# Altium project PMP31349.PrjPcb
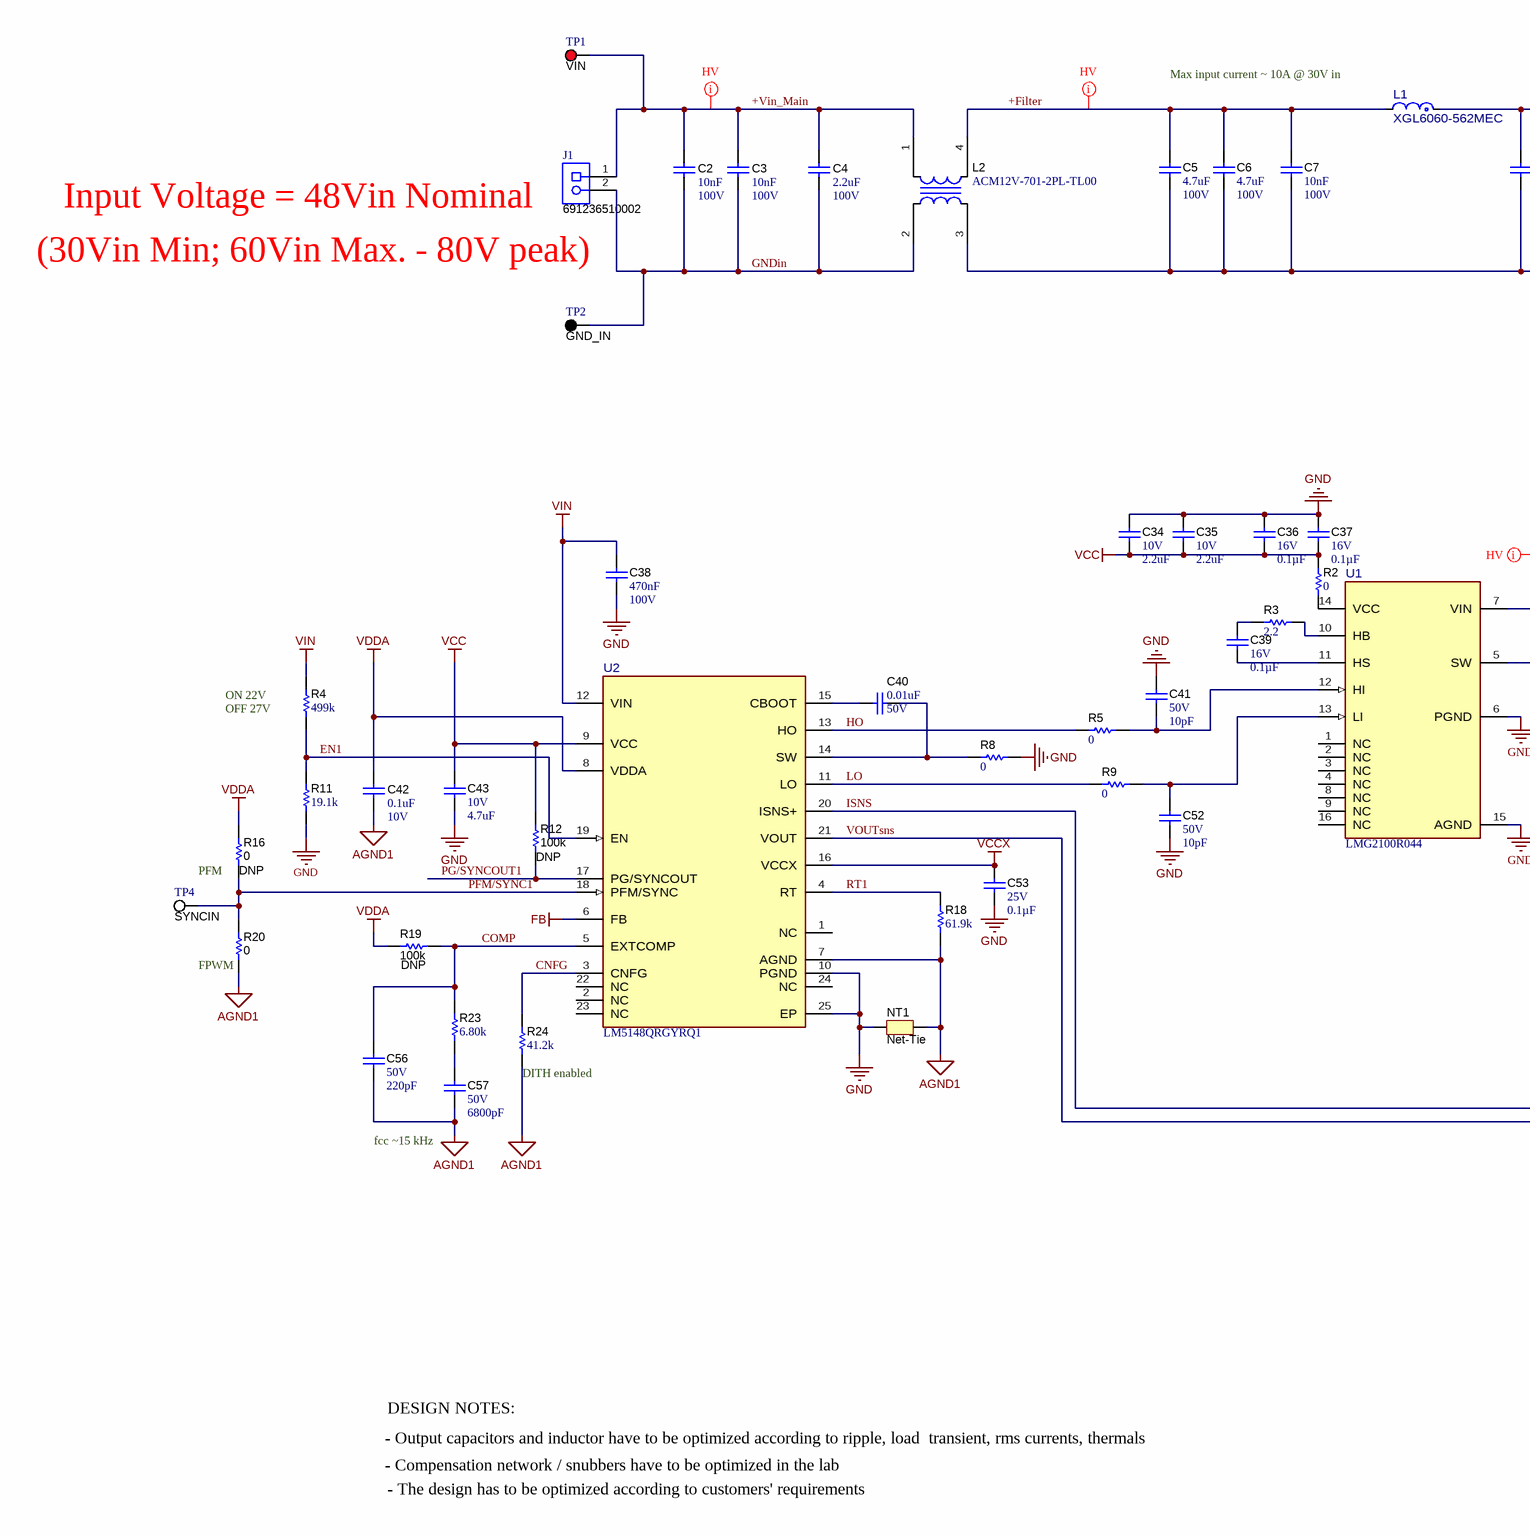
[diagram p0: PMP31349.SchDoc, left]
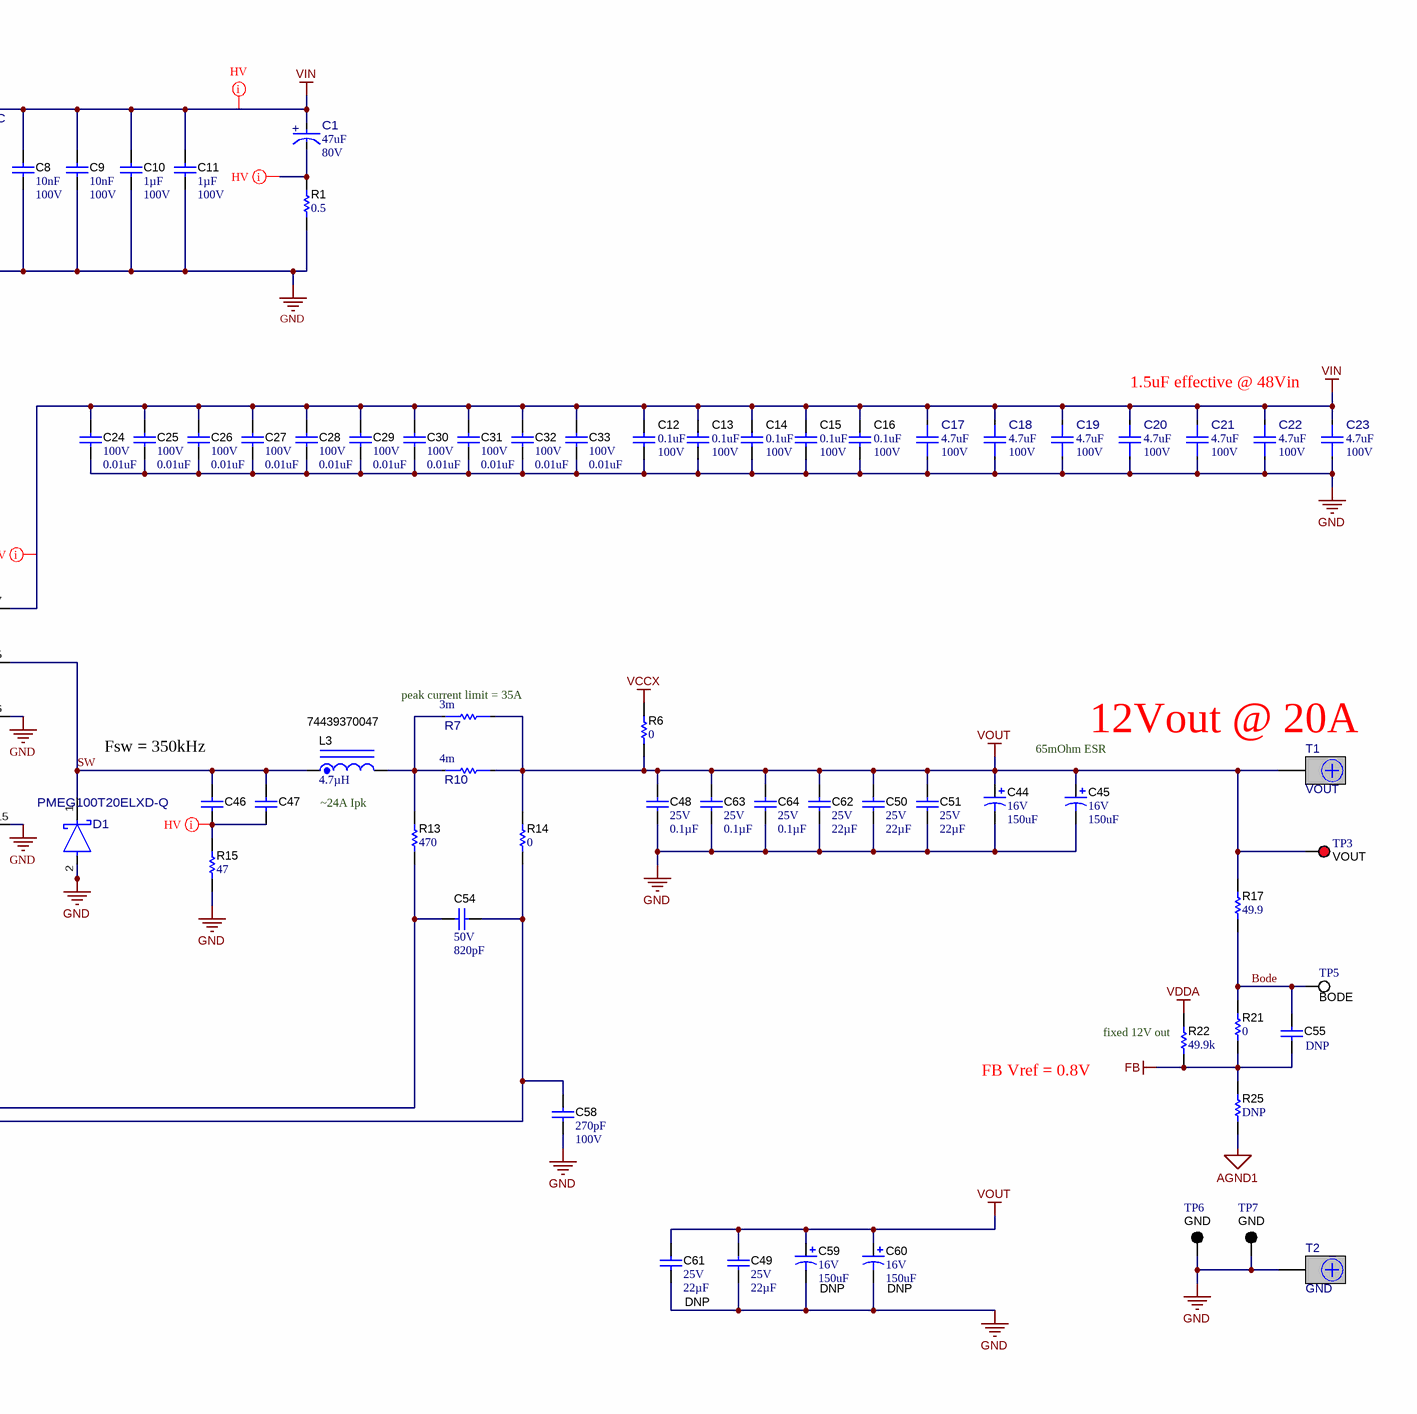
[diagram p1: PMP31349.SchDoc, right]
CopyrightYear: 2024; PCB_Layout: Who did the Layout?; PCB_Rev: B; PRJ_Customer: Public Release; PRJ_Engineer: S.Panaro; PRJ_Number: PMP31349; PRJ_Title: 240W GaN Board; SCH_Rev: B; TechSupport: http://www.ti.com/support; TID: N/A
2 sheets, 110 parts. Net scope: global (net labels, ports and power ports of the same name join across sheets).
Board file: PMP31349.PcbDoc
Sheets:
  PMP31349.SchDoc
  PMP31349_Hardware.SchDoc

## Sheet PMP31349.SchDoc
size 558 x 431 mm; Date: Not shown in title block; ApprovedBy: Not shown in title block; CheckedBy: Not shown in title block; Author: Not shown in title block; CompanyName: Not shown in title block; Engineer: Not shown in title block; Organization: Not shown in title block; Address1: Not shown in title block; Address2: Not shown in title block; Address3: Not shown in title block; Address4: Not shown in title block; DocumentNumber: 1; Revision: Use project parameter SCH_Rev; SheetNumber: 1; SheetTotal: 2; PageSetup: Record=PageOptions¦CenterHorizontal=True¦CenterVertical=True¦PrintScale=1.00¦XCorrection=1.00¦YCorrection=1.00¦PrintKind=0¦BorderSize=5000000¦LeftOffset=0¦BottomOffset=0¦Orientation=2¦PaperLength=1000¦PaperWidth=1000¦Scale=100¦PaperSource=15¦PrintQuality=600¦MediaType=1¦DitherType=10¦PaperKind=Letter¦PrintScaleMode=1; SPICEModelCacheOPLTMGFQ: <root> / <DocumentId>OPLTMGFQ</DocumentId> / </root>

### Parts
C1  ValueDisplayed: 47uF  VDC_V: 80V  [FP-EEHZA1K470P_RADIAL_SMT-MFG]  (hidden comment: EEHZA1K470P)
C2  Cap_F: 10nF  VDC_V: 100V  [0603_HV]  (hidden comment: GCM188R72A103KA37J)
C3  Cap_F: 10nF  VDC_V: 100V  [0603_HV]  (hidden comment: GCM188R72A103KA37J)
C4  VDC_V: 100V  ValueDisplayed: 2.2uF  [1206_180]  (hidden comment: CGA5L3X7S2A225K160AB)
C5  ValueDisplayed: 4.7uF  VDC_V: 100V  [1210_220]  (hidden comment: C3225X7S2A475K200AB)
C6  ValueDisplayed: 4.7uF  VDC_V: 100V  [1210_220]  (hidden comment: CGA6M3X7S2A475K200AB)
C7  Cap_F: 10nF  VDC_V: 100V  [0603L]  (hidden comment: GCM188R72A103KA37J)
C8  Cap_F: 10nF  VDC_V: 100V  [0603L]  (hidden comment: GCM188R72A103KA37J)
C9  Cap_F: 10nF  VDC_V: 100V  [0603L]  (hidden comment: GCM188R72A103KA37J)
C10  Cap_F: 1µF  VDC_V: 100V  [0805_150]  (hidden comment: 08051C105K4Z2A)
C11  Cap_F: 1µF  VDC_V: 100V  [0805_150]  (hidden comment: 08051C105K4Z2A)
C12  VDC_V: 100V  ValueDisplayed: 0.1uF  [0603L]  (hidden comment: GCJ188R72A104KA01D)
C13  VDC_V: 100V  ValueDisplayed: 0.1uF  [0603L]  (hidden comment: GCJ188R72A104KA01D)
C14  VDC_V: 100V  ValueDisplayed: 0.1uF  [0603L]  (hidden comment: GCJ188R72A104KA01D)
C15  VDC_V: 100V  ValueDisplayed: 0.1uF  [0603L]  (hidden comment: GCJ188R72A104KA01D)
C16  VDC_V: 100V  ValueDisplayed: 0.1uF  [0603L]  (hidden comment: GCJ188R72A104KA01D)
C17  ValueDisplayed: 4.7uF  VDC_V: 100V  [FP-GCJ32DC72A475KE01L_1210-MFG]  (hidden comment: GCJ32DC72A475KE01L)
C18  ValueDisplayed: 4.7uF  VDC_V: 100V  [FP-GCJ32DC72A475KE01L_1210-MFG]  (hidden comment: GCJ32DC72A475KE01L)
C19  ValueDisplayed: 4.7uF  VDC_V: 100V  [FP-GCJ32DC72A475KE01L_1210-MFG]  (hidden comment: GCJ32DC72A475KE01L)
C20  ValueDisplayed: 4.7uF  VDC_V: 100V  [FP-GCJ32DC72A475KE01L_1210-MFG]  (hidden comment: GCJ32DC72A475KE01L)
C21  ValueDisplayed: 4.7uF  VDC_V: 100V  [FP-GCJ32DC72A475KE01L_1210-MFG]
C22  ValueDisplayed: 4.7uF  VDC_V: 100V  [FP-GCJ32DC72A475KE01L_1210-MFG]
C23  ValueDisplayed: 4.7uF  VDC_V: 100V  [FP-GCJ32DC72A475KE01L_1210-MFG]
C24  VDC_V: 100V  ValueDisplayed: 0.01uF  [0402]  (hidden comment: CGA2B3X7S2A103K050BB)
C25  VDC_V: 100V  ValueDisplayed: 0.01uF  [0402]  (hidden comment: CGA2B3X7S2A103K050BB)
C26  VDC_V: 100V  ValueDisplayed: 0.01uF  [0402]  (hidden comment: CGA2B3X7S2A103K050BB)
C27  VDC_V: 100V  ValueDisplayed: 0.01uF  [0402]  (hidden comment: CGA2B3X7S2A103K050BB)
C28  VDC_V: 100V  ValueDisplayed: 0.01uF  [0402]  (hidden comment: CGA2B3X7S2A103K050BB)
C29  VDC_V: 100V  ValueDisplayed: 0.01uF  [0402]  (hidden comment: CGA2B3X7S2A103K050BB)
C30  VDC_V: 100V  ValueDisplayed: 0.01uF  [0402]  (hidden comment: CGA2B3X7S2A103K050BB)
C31  VDC_V: 100V  ValueDisplayed: 0.01uF  [0402]  (hidden comment: CGA2B3X7S2A103K050BB)
C32  VDC_V: 100V  ValueDisplayed: 0.01uF  [0402]  (hidden comment: CGA2B3X7S2A103K050BB)
C33  VDC_V: 100V  ValueDisplayed: 0.01uF  [0402]  (hidden comment: CGA2B3X7S2A103K050BB)
C34  VDC_V: 10V  ValueDisplayed: 2.2uF  [0402_065]  (hidden comment: C1005X7S1A225K050BC)
C35  VDC_V: 10V  ValueDisplayed: 2.2uF  [0402_065]  (hidden comment: C1005X7S1A225K050BC)
C36  VDC_V: 16V  ValueDisplayed: 0.1µF  [0402]  (hidden comment: GCM155R71C104JA55D)
C37  VDC_V: 16V  ValueDisplayed: 0.1µF  [0402]  (hidden comment: GCM155R71C104JA55D)
C38  Cap_F: 470nF  VDC_V: 100V  [0805_HV]  (hidden comment: 08051C474KAT2A)
C39  VDC_V: 16V  ValueDisplayed: 0.1µF  [0402]  (hidden comment: GCM155R71C104JA55D)
C40  ValueDisplayed: 0.01uF  Value2: 50V  [0402L]  (hidden comment: GRM155R71H103KA88D)
C41  VDC_V: 50V  ValueDisplayed: 10pF  [0402L]  (hidden comment: GRM1555C1H100FA01D)
C42  value 0.1uF  Value2: 10V  [0402L]  (hidden comment: C0402C104K8RACAUTO)
C43  VDC_V: 10V  ValueDisplayed: 4.7uF  [0603]  (hidden comment: C1608X7S1A475K080AC)
C44  VDC_V: 16V  ValueDisplayed: 150uF  [7343-31]  (hidden comment: T598D157M016ATE065)
C45  VDC_V: 16V  ValueDisplayed: 150uF  [7343-31]  (hidden comment: T598D157M016ATE065)
C46  C1005C0G2A331J050BE  [0402]  (value not drawn)
C47  C1005C0G2A331J050BE  [0402]  (value not drawn)
C48  VDC_V: 25V  ValueDisplayed: 0.1µF  [0402]  (hidden comment: CGA2B3X7R1E104K050BB)
C49  VDC_V: 25V  ValueDisplayed: 22µF  [1210_270]
C50  VDC_V: 25V  ValueDisplayed: 22µF  [1210_270]  (hidden comment: TMK325B7226KMHP)
C51  VDC_V: 25V  ValueDisplayed: 22µF  [1210_270]  (hidden comment: TMK325B7226KMHP)
C52  VDC_V: 50V  ValueDisplayed: 10pF  [0402L]  (hidden comment: GRM1555C1H100FA01D)
C53  VDC_V: 25V  ValueDisplayed: 0.1µF  [0402L]  (hidden comment: CGA2B3X7R1E104K050BB)
C54  VDC_V: 50V  ValueDisplayed: 820pF  [0402]  (hidden comment: GRM1555C1H821JA01D)
C55  ValueDisplayed: DNP  [0402L]  (hidden comment: GRM1555C1H100FA01D)
C56  VDC_V: 50V  ValueDisplayed: 220pF  [0402]  (hidden comment: CGA2B2C0G1H221J050BA)
C57  VDC_V: 50V  ValueDisplayed: 6800pF  [0402]  (hidden comment: GRM155R71H682KA88D)
C58  ValueDisplayed: 270pF  VDC_V: 100V  [0402L]  (hidden comment: GRM155R72A271KA01D)
C59  DNP  VDC_V: 16V  ValueDisplayed: 150uF  [7343-31]
C60  DNP  VDC_V: 16V  ValueDisplayed: 150uF  [7343-31]
C61  DNP  VDC_V: 25V  ValueDisplayed: 22µF  [1210_270]
C62  VDC_V: 25V  ValueDisplayed: 22µF  [1210_270]  (hidden comment: TMK325B7226KMHP)
C63  VDC_V: 25V  ValueDisplayed: 0.1µF  [0402]  (hidden comment: CGA2B3X7R1E104K050BB)
C64  VDC_V: 25V  ValueDisplayed: 0.1µF  [0402]  (hidden comment: CGA2B3X7R1E104K050BB)
D1  PMEG100T20ELXD-Q  [FP-SS16HE_SOD-323HE-MFG]
J1  691236510002  [Wurth_691236510002]
L1  XGL6060-562MEC  [FP-XGL6060-562MEC_SMT2_6MM51_6MM71-MFG]
L2  PartNumber: ACM12V-701-2PL-TL00  [TDK_ACM12V]
L3  74439370047  ValueDisplayed: 4.7µH  [WE-XHMI_1510]
NT1  Net-Tie  [Net-Tie_10mil]  (net tie, no BOM)
R1  ValueDisplayed: 0.5  [2010]  (hidden comment: CSRN2010FKR500)
R2  ValueDisplayed: 0  [0402]  (hidden comment: CRCW04020000Z0ED)
R3  ValueDisplayed: 2.2  [0402]  (hidden comment: CRCW04022R20JNED)
R4  ValueDisplayed: 499k  [0402]  (hidden comment: CRCW0402499KFKED)
R5  ValueDisplayed: 0  [0603]  (hidden comment: RC0603JR-070RL)
R6  ValueDisplayed: 0  [0402]  (hidden comment: CRCW04020000Z0ED)
R7  value 3m  [FP-KRL2012E-M-R003-F-T5_0805-MFG]  (hidden comment: KRL2012E-M-R003-F-T5)
R8  ValueDisplayed: 0  [0402L]  (hidden comment: CRCW04020000Z0ED)
R9  ValueDisplayed: 0  [0603]  (hidden comment: RC0603JR-070RL)
R10  value 4m  [FP-KRL2012E-M-R004-F-T5_2012-MFG]  (hidden comment: KRL2012E-M-R004-F-T5)
R11  ValueDisplayed: 19.1k  [0402]  (hidden comment: CRCW040219K1FKED)
R12  DNP  ValueDisplayed: 100k  [0402L]
R13  ValueDisplayed: 470  [0402]  (hidden comment: RC0402FR-07470RL)
R14  ValueDisplayed: 0  [0402L]  (hidden comment: CRCW04020000Z0ED)
R15  ValueDisplayed: 47  [1206]  (hidden comment: CRCW120647R0JNEA)
R16  DNP  ValueDisplayed: 0  [0402L]
R17  ValueDisplayed: 49.9  [0603L]  (hidden comment: CRCW060349R9FKEA)
R18  ValueDisplayed: 61.9k  [0402]  (hidden comment: CRCW040261K9FKED)
R19  DNP  ValueDisplayed: 100k  [0402L]
R20  ValueDisplayed: 0  [0402L]
R21  ValueDisplayed: 0  [0402L]  (hidden comment: CRCW04020000Z0ED)
R22  ValueDisplayed: 49.9k  [0402L]  (hidden comment: CRCW040249K9FKED)
R23  ValueDisplayed: 6.80k  [0402]  (hidden comment: RC0402FR-076K8L)
R24  ValueDisplayed: 41.2k  [0402]  (hidden comment: CRCW040241K2FKED)
R25  ValueDisplayed: DNP  [0402L]  (hidden comment: CRCW04027K15FKED)
T1  VOUT  [CB35-36-CY]
T2  GND  [CB35-36-CY]
TP1  VIN  [Keystone5010]
TP2  GND_IN  [Keystone5011]
TP3  VOUT  [Keystone5010]
TP4  SYNCIN  [Keystone5002]
TP5  BODE  [Keystone5002]
TP6  GND  [Keystone5011]
TP7  GND  [Keystone5011]
U1  LMG2100R044  [RAR0016A-MFG]
U2  LM5148QRGYRQ1  [RGY0024E-MFG]

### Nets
AGND1: C42.1 C56.2 C57.2 NT1.2 R18.1 R20.2 R24.1 R25.1 U2.7(AGND)
FB: C55.2 R21.1 R22.1 R25.2 U2.6(FB)
GND: C5.1 C6.1 C7.2 C8.2 C9.2 C10.2 C11.2 C12.2 C13.2 C14.2 C15.2 C16.2 C17.1 C18.1 C19.1 C20.1 C21.1 C22.1 C23.1 C24.2 C25.1 C26.1 C27.1 C28.2 C29.1 C30.1 C31.1 C32.1 C33.1 C34.1 C35.1 C36.1 C37.1 C38.2 C41.1 C43.2 C44.2(-) C45.2(-) C48.2 C49.2 C50.2 C51.2 C52.2 C53.2 C58.1 C59.2(-) C60.2(-) C61.2 C62.2 C63.2 C64.2 D1.2(Anode) L2.3 NT1.1 R1.1 R8.2 R11.1 R15.1 T2.1 TP6.1 TP7.1 U1.6(PGND) U1.15(AGND) U2.10(PGND) U2.25(EP)
VCC: C34.2 C35.2 C36.2 C37.2 C43.1 R2.2 R12.2 U2.9(VCC)
VCCX: C53.1 R6.2 U2.16(VCCX)
VDDA: C42.2 R16.1 R19.2 R22.2 U2.8(VDDA)
VIN: C1.2(ANODE) C8.1 C9.1 C10.1 C11.1 C12.1 C13.1 C14.1 C15.1 C16.1 C17.2 C18.2 C19.2 C20.2 C21.2 C22.2 C23.2 C24.1 C25.2 C26.2 C27.2 C28.1 C29.2 C30.2 C31.2 C32.2 C33.2 C38.1 L1.1 R4.2 U1.7(VIN) U2.12(VIN)
VOUT: C44.1(+) C45.1(+) C48.1 C49.1 C50.1 C51.1 C59.1(+) C60.1(+) C61.1 C62.1 C63.1 C64.1 R6.1 R7.2 R10.2 R14.2 R17.2 T1.1 TP3.1
+Filter: C5.2 C6.2 C7.1 L1.2 L2.4
+Vin_Main: C2.1 C3.1 C4.1 J1.1 L2.1 TP1.1
Bode: C55.1 R17.1 R21.2 TP5.1
CNFG: R24.2 U2.3(CNFG)
COMP: C56.1 R19.1 R23.2 U2.5(EXTCOMP)
EN1: R4.1 R11.2 U2.19(EN)
GNDin: C2.2 C3.2 C4.2 J1.2 L2.2 TP2.1
HO: R5.1 U2.13(HO)
ISNS: C54.2 R13.1 U2.20(ISNS+)
LO: R9.1 U2.11(LO)
PFM/SYNC1: R16.2 R20.1 TP4.1 U2.18(PFM/SYNC)
PG/SYNCOUT1: R12.1 U2.17(PG/SYNCOUT)
RT1: R18.2 U2.4(RT)
SW: C46.1 C47.1 D1.1(Cathode) L3.1 U1.5(SW)
VOUTsns: C54.1 C58.2 R14.1 U2.21(VOUT)
NetC1_1: C1.1(CATHODE) R1.2
NetC39_1: C39.1 R3.2
NetC39_2: C39.2 U1.11(HS)
NetC40_1: C40.1 U2.15(CBOOT)
NetC40_2: C40.2 R8.1 U2.14(SW)
NetC41_2: C41.2 R5.2 U1.12(HI)
NetC46_2: C46.2 C47.2 R15.2
NetC52_1: C52.1 R9.2 U1.13(LI)
NetC57_1: C57.1 R23.1
NetL3_2: L3.2 R7.1 R10.1 R13.2
NetR2_1: R2.1 U1.14(VCC)
NetR3_1: R3.1 U1.10(HB)

Not connected (* = marked no-connect by the designer): U1 1(NC) 2(NC) 3(NC) 4(NC) 8(NC) 9(NC) 16(NC); U2 1(NC) 2(NC) 22(NC) 23(NC) 24(NC)

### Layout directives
net class HV: +Filter, +Vin_Main, NetC1_1, NetC46_2, VIN

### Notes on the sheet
- (near L1) Max input current ~ 10A @ 30V in
- (near J1) Input Voltage = 48Vin Nominal
- (30Vin Min; 60Vin Max. - 80V peak)
- 1.5uF effective @ 48Vin
- (near R4) ON 22V
- (near R4) OFF 27V
- (near R7) peak current limit = 35A
- (near C46) Fsw = 350kHz
- 65mOhm ESR
- (near T1) 12Vout @ 20A
- (near L3) |4A Ipk
- PFM
- (near R20) FPWM
- (near R22) fixed 12V out
- (near R24) DITH enabled
- FB Vref = 0.8V
- fcc
  5 kHz
- - Output capacitors and inductor have to be optimized according to ripple, load  transient, rms currents, thermals
- DESIGN NOTES:
- - Compensation network / snubbers have to be optimized in the lab
- - The design has to be optimized according to customers' requirements

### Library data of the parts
C1 = CMP-0120543-1: Conductive Polymer Hybrid Aluminum Electrolytic Capacitors 47uF ±20% 80V RADIAL SMT 10x10.2mm; Manufacturer: Panasonic; AEC Grade: Grade 2; AEC Qualified: Yes; Cap_F: 47µF; IRMS_A: 1.7A; SizeZ_mm: 10.5mm; Dissipation Factor: 0.08; Esr: 36m; Leakage Current: 37.6uA; Life: 10000Hours; Value: 47µF
C2 = CMP-0084773-1: CAP, CERM, 0.01 µF, 100 V,+/- 10%, X7R, AEC-Q200 Grade 1, 0603; Manufacturer: MuRata; Polarized: N; Value: 0.01uF; ValueDisplayed: 0.01µF; U/M: EA; TaMin_C: -55°C; TaMax_C: 125°C; Cap_Case: 0603; AEC Category: Q200; AEC Grade: 1; AEC Qualified: Y; SizeArea_mm2: 1.28; SizeAreaWB_mm2: 4.68; SizeX_mm: 1.6; SizeY_mm: 0.8
C3 C7-C9 = CMP-0084773-1: CAP, CERM, 0.01 µF, 100 V,+/- 10%, X7R, AEC-Q200 Grade 1, 0603; Manufacturer: MuRata; TaMin_C: -55°C; Polarized: N; SizeAreaWB_mm2: 4.68; U/M: EA; Value: 0.01uF; TaMax_C: 125°C; SizeZ_mm: 1; SizeX_mm: 1.6; SizeY_mm: 0.8; Cap_Case: 0603; SizeArea_mm2: 1.28; AEC Qualified: Y; AEC Category: Q200; ValueDisplayed: 0.01µF
C4 = CMP-0008790-2: CAP, CERM, 2.2 uF, 100 V, +/- 10%, X7S, AEC-Q200 Grade 1, 1206; Manufacturer: TDK; TaMin_C: -55°C; ESR_ohm: 5.718m; Polarized: N; SizeAreaWB_mm2: 10.92; Value1: 0.005718 ohm; U/M: EA; Value: 2.2uF; TaMax_C: 125°C; SizeZ_mm: 1.8; SizeX_mm: 3.2; SizeY_mm: 1.6; SizeArea_mm2: 5.12; AEC Qualified: Y; Cap_F: 2.2µF; IRMS_A: 3.03632A; AEC Grade: 1; AEC Category: Q200
C5 = CMP-0009134-2: CAP, CERM, 4.7 uF, 100 V, +/- 10%, X7S, 1210; Manufacturer: TDK; AEC Qualified: N; SizeZ_mm: 2.2; Cap_F: 4.7µF; TaMin_C: -55°C; ESR_ohm: 4.236m; SizeAreaWB_mm2: 14.7; Value1: 0.004236 ohm; U/M: EA; Value: 4.7uF; TaMax_C: 125°C; SizeX_mm: 3.2; SizeY_mm: 2.5; SizeArea_mm2: 8; IRMS_A: 3.57337A; AEC Category: Q200
C6 = CMP-0009150-2: CAP, CERM, 4.7 uF, 100 V, +/- 10%, X7S, AEC-Q200 Grade 1, 1210; Manufacturer: TDK; AEC Qualified: Y; SizeZ_mm: 2.2; Cap_F: 4.7µF; AEC Grade: 1; TaMin_C: -55°C; ESR_ohm: 4.236m; Polarized: N; SizeAreaWB_mm2: 14.7; Value1: 0.004236 ohm; U/M: EA; Value: 4.7uF; TaMax_C: 125°C; SizeX_mm: 3.2; SizeY_mm: 2.5; SizeArea_mm2: 8; IRMS_A: 3.57337A; AEC Category: Q200
C10 C11 = CMP-0861070-1: CAP, CERM, 1 µF, 100 V,+/- 10%, X7R, AEC-Q200 Grade 1, 0805; Manufacturer: AVX; Polarized: N; Value: 1uF; U/M: EA; TaMin_C: -55°C; TaMax_C: 125°C; Cap_Case: 0805; AEC Category: Q200; AEC Grade: 1; AEC Qualified: Y; SizeArea_mm2: 2.5; SizeAreaWB_mm2: 6.75; SizeX_mm: 2; SizeY_mm: 1.25; SizeZ_mm: 1.5
C12-C16 = CMP-0064935-4: CAP, CERM, 0.1 uF, 100 V,+/- 10%, X7R, AEC-Q200 Grade 1, 0603; Manufacturer: MuRata; TaMin_C: -55°C; Polarized: N; SizeAreaWB_mm2: 4.68; Value1: Unknown; U/M: EA; Value: 0.1uF; TaMax_C: 125°C; SizeZ_mm: 1; SizeX_mm: 1.6; SizeY_mm: 0.8; Cap_Case: 0603; SizeArea_mm2: 1.28; AEC Qualified: Y; Cap_F: 100nF; AEC Category: Q200
C17-C20 = CMP-0093675-1: 4.7uF ±10% 100V Ceramic Capacitor X7S 1210 (3225 Metric); Manufacturer: Murata; AEC Qualified: Yes; TempCo: 22%; SizeZ_mm: 2.3mm; Cap_F: 4.7µF; AEC Grade: Grade 1; Value: 4.7µF
C21-C23 = CMP-0093675-1: 4.7uF ±10% 100V Ceramic Capacitor X7S 1210 (3225 Metric); Manufacturer: Murata; PartNumber: GCJ32DC72A475KE01L; AEC Qualified: Yes; TempCo: 22%; SizeZ_mm: 2.3mm; Cap_F: 4.7µF; AEC Grade: Grade 1; Value: 4.7µF
C24-C33 = CMP-0006333-2: CAP, CERM, 0.01 uF, 100 V, +/- 10%, X7S, AEC-Q200 Grade 1, 0402; Manufacturer: TDK; TaMin_C: -55°C; ESR_ohm: 0.4102; Polarized: N; SizeAreaWB_mm2: 3; Value1: 0.410191 ohm; U/M: EA; Value: 0.01uF; TaMax_C: 125°C; SizeZ_mm: 0.6; SizeX_mm: 1; SizeY_mm: 0.5; AEC Qualified: Y; Cap_F: 10nF; IRMS_A: 291.729mA; AEC Category: Q200
C34 C35 = CMP-0006302-2: CAP, CERM, 2.2 uF, 10 V, +/- 10%, X7S, 0402; Manufacturer: TDK; TaMin_C: -55°C; ESR_ohm: 5.925m; Polarized: N; SizeAreaWB_mm2: 3; Value1: 0.005925 ohm; U/M: EA; Value: 2.2uF; TaMax_C: 125°C; SizeZ_mm: 0.65; SizeX_mm: 1; SizeY_mm: 0.5; Cap_F: 2.2µF; IRMS_A: 2.0559A; AEC Category: Q200
C36 C37 C39 = CMP-0080702-1: CAP, CERM, 0.1 µF, 16 V,+/- 5%, X7R, AEC-Q200 Grade 1, 0402; Manufacturer: MuRata; Cap_F: 100nF; SizeAreaWB_mm2: 3; SizeArea_mm2: 0.5; AEC Qualified: Y; AEC Category: Q200; Value: 0.1uF; TaMax_C: 125°C; SizeZ_mm: 0.6; AEC Grade: 1; Polarized: N; TaMin_C: -55°C; U/M: EA
C38 = CMP-0750097-1: CAP, CERM, 0.47 µF, 100 V,+/- 10%, X7R, 0805; Manufacturer: AVX; ValueDisplayed: 0.47µF; SizeArea_mm2: 2.5; Value: 0.47uF; Cap_Case: 0805; TaMin_C: -55°C; SizeAreaWB_mm2: 6.75; TaMax_C: 125°C; AEC Category: Q200; SizeX_mm: 2; Polarized: N; SizeY_mm: 1.25; SizeZ_mm: 1.45; U/M: EA
C40 = CMP-0006674-2: CAP, CERM, 0.01 uF, 50 V, +/- 10%, X7R, 0402; Manufacturer: MuRata; Polarized: N; Value: 0.01uF; U/M: EA; Cap_F: 10nF; Value1: Unknown; TaMin_C: -55°C; TaMax_C: 125°C; Cap_Case: 0402; AEC Category: Q200; SizeArea_mm2: 0.5; SizeAreaWB_mm2: 3; SizeX_mm: 1; SizeZ_mm: 0.6
C41 C52 = CMP-0064916-2: CAP, CERM, 10 pF, 50 V,+/- 1%, C0G/NP0, 0402; Manufacturer: MuRata; TaMin_C: -55°C; Polarized: N; SizeAreaWB_mm2: 3; Value1: Unknown; U/M: EA; Value: 10pF; TaMax_C: 125°C; SizeZ_mm: 0.6; SizeX_mm: 1; SizeY_mm: 0.5; Cap_Case: 0402; AEC Category: Q200
C42 = CMP-0079150-1: CAP, CERM, 0.1 µF, 10 V,+/- 10%, X7R, AEC-Q200 Grade 1, 0402; Manufacturer: Kemet; Polarized: N; ValueDisplayed: 0.1µF; U/M: EA; Cap_F: 100nF; TaMin_C: -55°C; TaMax_C: 125°C; Cap_Case: 0402; AEC Category: Q200; AEC Grade: 1; AEC Qualified: Y; SizeArea_mm2: 0.5; SizeAreaWB_mm2: 3; SizeZ_mm: 0.6
C43 = CMP-0007058-4: CAP, CERM, 4.7 uF, 10 V, +/- 10%, X7S, 0603; Manufacturer: TDK; TaMin_C: -55°C; Polarized: N; SizeAreaWB_mm2: 4.68; Value1: Unknown; U/M: EA; Value: 4.7uF; TaMax_C: 125°C; SizeZ_mm: 1; SizeX_mm: 1.6; SizeY_mm: 0.8; SizeArea_mm2: 1.28; Cap_F: 4.7µF; AEC Category: Q200
C44 C45 = CMP-0012660-3: CAP, Tantalum Polymer, 150 uF, 16 V, +/- 20%, 0.065 ohm, AEC-Q200 Grade 1, 7343-31 SMD; Manufacturer: Kemet; TaMin_C: -55°C; ESR_ohm: 65m; Polarized: Y; SizeAreaWB_mm2: 58.59; Value1: 0.05 ohm; Value: 150uF; TaMax_C: 125°C; SizeZ_mm: 3.1; SizeX_mm: 7.3; SizeY_mm: 4.3; SizeArea_mm2: 31.39; CompType: Capacitor; Cap_F: 150µF; IRMS_A: 1.9A; AEC Grade: 1; AEC Category: Q200
C46 C47 = CMP-0750160-1: CAP, CERM, 330 pF, 100 V,+/- 5%, C0G/NP0, 0402; Manufacturer: TDK; SizeZ_mm: 0.6; SizeArea_mm2: 0.5; Value: 330pF; SizeX_mm: 1; AEC Qualified: N; AEC Category: Q200; U/M: EA; SizeAreaWB_mm2: 3; TaMin_C: -55°C; Value2: 100V; TaMax_C: 125°C
C48 C63 C64 = CMP-0080610-1: CAP, CERM, 0.1 µF, 25 V,+/- 10%, X7R, AEC-Q200 Grade 1, 0402; Manufacturer: TDK; TaMin_C: -55°C; Polarized: N; SizeAreaWB_mm2: 3; U/M: EA; Value: 0.1uF; TaMax_C: 125°C; SizeZ_mm: 0.6; SizeX_mm: 1; SizeY_mm: 0.5; AEC Qualified: Y; Cap_F: 100nF; AEC Category: Q200
C49 C61 = CMP-0080552-1: CAP, CERM, 22 µF, 25 V,+/- 10%, X7R, AEC-Q200 Grade 1, 1210; Manufacturer: Taiyo Yuden; PartNumber: TMK325B7226KMHP; TaMin_C: -55°C; Polarized: N; SizeAreaWB_mm2: 14.7; U/M: EA; Value: 22uF; TaMax_C: 125°C; SizeZ_mm: 2.7; SizeX_mm: 3.2; SizeY_mm: 2.5; Cap_Case: 1210; SizeArea_mm2: 8; AEC Qualified: Y; AEC Grade: 1; AEC Category: Q200
C50 C51 C62 = CMP-0080552-1: CAP, CERM, 22 µF, 25 V,+/- 10%, X7R, AEC-Q200 Grade 1, 1210; Manufacturer: Taiyo Yuden; TaMin_C: -55°C; Polarized: N; SizeAreaWB_mm2: 14.7; U/M: EA; Value: 22uF; TaMax_C: 125°C; SizeZ_mm: 2.7; SizeX_mm: 3.2; SizeY_mm: 2.5; Cap_Case: 1210; SizeArea_mm2: 8; AEC Qualified: Y; AEC Grade: 1; AEC Category: Q200
C53 = CMP-0080610-1: CAP, CERM, 0.1 µF, 25 V,+/- 10%, X7R, AEC-Q200 Grade 1, 0402; Manufacturer: TDK; TaMin_C: -55°C; Polarized: N; SizeAreaWB_mm2: 3; U/M: EA; Value: 0.1uF; TaMax_C: 125°C; SizeZ_mm: 0.6; SizeX_mm: 1; SizeY_mm: 0.5; Cap_Case: 0402; AEC Qualified: Y; Cap_F: 100nF; AEC Category: Q200
C54 = CMP-0006493-2: CAP, CERM, 820 pF, 50 V, +/- 5%, C0G/NP0, 0402; Manufacturer: MuRata; TaMin_C: -55°C; Polarized: N; SizeAreaWB_mm2: 3; Value1: Unknown; U/M: EA; Value: 820pF; TaMax_C: 125°C; SizeZ_mm: 0.6; SizeX_mm: 1; SizeY_mm: 0.5; AEC Category: Q200
C55 = CMP-0064916-2: CAP, CERM, 10 pF, 50 V,+/- 1%, C0G/NP0, 0402; Manufacturer: MuRata; TaMin_C: -55°C; Polarized: N; SizeAreaWB_mm2: 3; Value1: Unknown; U/M: EA; Value: 10pF; TaMax_C: 125°C; SizeZ_mm: 0.6; SizeX_mm: 1; SizeY_mm: 0.5; Cap_Case: 0402; Value2: 50V; AEC Category: Q200
C56 = CMP-0079606-1: CAP, CERM, 220 pF, 50 V,+/- 5%, C0G/NP0, AEC-Q200 Grade 1, 0402; Manufacturer: TDK; TaMin_C: -55°C; Polarized: N; SizeAreaWB_mm2: 3; U/M: EA; Value: 220pF; TaMax_C: 125°C; SizeZ_mm: 0.6; SizeX_mm: 1; SizeY_mm: 0.5; AEC Qualified: Y; AEC Category: Q200
C57 = CMP-0006696-2: CAP, CERM, 6800 pF, 50 V, +/- 10%, X7R, 0402; Manufacturer: MuRata; TaMin_C: -55°C; Polarized: N; SizeAreaWB_mm2: 3; Value1: Unknown; U/M: EA; Value: 6800pF; TaMax_C: 125°C; SizeZ_mm: 0.6; SizeX_mm: 1; SizeY_mm: 0.5; Cap_F: 6.8nF; AEC Category: Q200
C58 = CMP-0006705-2: CAP, CERM, 270 pF, 100 V, +/- 10%, X7R, 0402; Manufacturer: MuRata; Polarized: N; Value: 270pF; U/M: EA; Value1: Unknown; TaMin_C: -55°C; TaMax_C: 125°C; Cap_Case: 0402; AEC Category: Q200; SizeArea_mm2: 0.5; SizeAreaWB_mm2: 3; SizeX_mm: 1; SizeZ_mm: 0.6
C59 C60 = CMP-0012660-3: CAP, Tantalum Polymer, 150 uF, 16 V, +/- 20%, 0.065 ohm, AEC-Q200 Grade 1, 7343-31 SMD; Manufacturer: Kemet; PartNumber: T598D157M016ATE065; TaMin_C: -55°C; ESR_ohm: 65m; Polarized: Y; SizeAreaWB_mm2: 58.59; Value1: 0.05 ohm; Value: 150uF; TaMax_C: 125°C; SizeZ_mm: 3.1; SizeX_mm: 7.3; SizeY_mm: 4.3; SizeArea_mm2: 31.39; CompType: Capacitor; Cap_F: 150µF; IRMS_A: 1.9A; AEC Grade: 1; AEC Category: Q200
D1 = CMP-0121148-1: Diode Schottky 100 V 2A Surface Mount; AEC Qualified: No; TJmax_C: 150°C
J1 = CMP-0079044-1: Terminal Block, 5.08mm, 2x1, R/A, TH; Manufacturer: Wurth Elektronik; Pitch_mm: 5.08; Cert_VDE: Y; Gender: Female; Voltage_V: 300V; Current_A: 20A; Row_Count: 1
L1 = CMP-0095663-1: 5.6 µH Shielded Inductor 12.6 A 11.7mOhm Max Nonstandard; Manufacturer: Coilcraft; Ind_H: 5.6µH; AEC Grade: Grade 1; Irms: 12.6A; Isat: 4.8A; Tolerance_%: 20%; Material: Composite; Self Resonant Frequency: 17MHz; AEC Qualified: Yes; Test Frequency: 1MHz; DCR_ohm: 11.7m; Shrouded: true; Value: 5.6uH; SizeZ_mm: 6.1mm; TaMin_C: -40°C; TaMax_C: +125°C
L2 = CMP-0084691-1: Coupled inductor,  ohm, AEC-Q200 Grade 1, SMD; Manufacturer: TDK; AEC Grade: 1; AEC Category: Q200; SizeZ_mm: 6; SizeX_mm: 12; AEC Qualified: Y; SizeAreaWB_mm2: 182; SizeArea_mm2: 132; SizeY_mm: 11
L3 = CMP-0084625-1: Inductor, Shielded, Metal Composite, 4.7 µH, 17 A, 0.00385 ohm, SMD; Manufacturer: Wurth Elektronik; AEC Qualified: N; SizeArea_mm2: 252.56; Value2: 17A; SizeX_mm: 15.4; Isat: 58A @ 30% inductance drop; Irms: 17A @ 40C rise; DCR_ohm: 3.85m; Value: 4.7uH; SizeAreaWB_mm2: 320.16; SizeZ_mm: 10; AEC Category: Q200; SizeY_mm: 16.4
NT1 = CMP-0078142-3: Single point connection between nets.
R1 = CMP-0016530-2: RES, 0.5, 1%, 1 W, 2010; Manufacturer: Stackpole Electronics Inc; Power_W: 1W; TempCo: 250 ppm/C; Value_Code: R500; U/M: EA; Value: 0.5; SizeX_mm: 5; SizeY_mm: 2.5; SizeZ_mm: 1.66; SizeArea_mm2: 12.5; AEC Category: Q200
R2 R6 R8 R14 R21 = CMP-0026822-3: RES, 0, 5%, 0.063 W, AEC-Q200 Grade 0, 0402; Manufacturer: Vishay-Dale; Power_W: 63mW; TempCo: 200 ppm/C; Value_Code: 0000; Value: 0; EIA_Code: E24; SizeX_mm: 1; SizeY_mm: 0.5; SizeZ_mm: 0.6; Value2: 0.063W; AEC Qualified: Y; VDC_V: 50V; AEC Category: Q200
R3 = CMP-0026898-3: RES, 2.2, 5%, 0.063 W, AEC-Q200 Grade 0, 0402; Manufacturer: Vishay-Dale; Power_W: 63mW; TempCo: 200 ppm/C; Value_Code: 2R20; Value: 2.2; EIA_Code: E24; SizeX_mm: 1; SizeY_mm: 0.5; SizeZ_mm: 0.6; Value2: 0.063W; AEC Qualified: Y; VDC_V: 50V; AEC Category: Q200; AEC Grade: 0
R4 = CMP-0026401-2: RES, 499 k, 1%, 0.063 W, AEC-Q200 Grade 0, 0402; Manufacturer: Vishay-Dale; Power_W: 63mW; TempCo: 100 ppm/C; Value: 499k; EIA_Code: E96; SizeX_mm: 1; SizeY_mm: 0.5; SizeZ_mm: 0.6; Value2: 0.063W; AEC Qualified: Y; VDC_V: 50V; AEC Category: Q200; AEC Grade: 0
R5 R9 = CMP-0025885-5: RES, 0, 5%, 0.1 W, 0603; Manufacturer: Yageo; Power_W: 100mW; TempCo: 200 ppm/C; Value_Code: 0000; Value: 0; EIA_Code: E24; SizeX_mm: 1.6; SizeZ_mm: 1; Value2: 0.1W; SizeArea_mm2: 1.28; AEC Qualified: N; VDC_V: 75V; AEC Category: Q200; SizeY_mm: 0.8; SizeAreaWB_mm2: 4.68
R7 = CMP-0090631-1: 3 mOhms ±1% 1W Chip Resistor Wide 0805 (2012 Metric), 0508 Automotive AEC-Q200, Current Sense Metal Foil; Manufacturer: Susumu; TempCo: 50ppm/°C; AEC Qualified: Yes; SizeZ_mm: 0.7mm; AEC Grade: Grade 0
R10 = CMP-0095678-1: 4 mOhms ±1% 1W Chip Resistor Wide 0805 (2012 Metric), 0508 Automotive AEC-Q200, Current Sense Metal Foil; Manufacturer: Susumu; AEC Grade: Grade 0; TempCo: 50ppm/°C; AEC Qualified: Yes; SizeZ_mm: 0.7mm
R11 = CMP-0026067-3: RES, 19.1 k, 1%, 0.063 W, AEC-Q200 Grade 0, 0402; Manufacturer: Vishay-Dale; Power_W: 63mW; TempCo: 100 ppm/C; Value_Code: 19k1; Value: 19.1k; EIA_Code: E96; SizeX_mm: 1; SizeY_mm: 0.5; SizeZ_mm: 0.6; Value2: 0.063W; AEC Qualified: Y; VDC_V: 50V; AEC Category: Q200; AEC Grade: 0
R12 R19 = CMP-0026753-1: RES, 100 k, 1%, 0.063 W, AEC-Q200 Grade 0, 0402; PartNumber: RMCF0402FT100K; Manufacturer: Stackpole Electronics Inc; Value: 100k; Power_W: 63mW; Value2: 0.063W; VDC_V: 50V; TempCo: 100 ppm/C; EIA_Code: E96; AEC Category: Q200; AEC Grade: 0; AEC Qualified: Y; SizeArea_mm2: 0.5; SizeX_mm: 1; SizeZ_mm: 0.6; U/M: EA
R13 = CMP-0026736-1: RES, 470, 1%, 0.063 W, 0402; Manufacturer: Yageo America; Power_W: 63mW; TempCo: 100 ppm/C; Value_Code: 470R; U/M: EA; Value: 470; SizeX_mm: 1; SizeY_mm: 0.5; SizeZ_mm: 0.6; Value2: 0.063W; AEC Qualified: N; VDC_V: 50V; AEC Category: Q200
R15 = CMP-0018687-3: RES, 47, 5%, 0.25 W, AEC-Q200 Grade 0, 1206; Manufacturer: Vishay-Dale; Power_W: 250mW; TempCo: 200 ppm/C; Value_Code: 47R0; Value: 47; EIA_Code: E24; SizeX_mm: 3.2; SizeY_mm: 1.6; SizeZ_mm: 1.35; Value2: 0.25W; SizeArea_mm2: 5.12; AEC Qualified: Y; VDC_V: 200V; AEC Category: Q200; AEC Grade: 0
R16 R20 = CMP-0081856-1: RES, 0, 0%, 0.2 W, AEC-Q200 Grade 0, 0402; PartNumber: CRCW04020000Z0EDHP; Manufacturer: Vishay-Dale; SizeAreaWB_mm2: 3; SizeArea_mm2: 0.5; AEC Qualified: Y; AEC Category: Q200; Value: 0; SizeZ_mm: 0.6; Power_W: 200mW; VDC_V: 50V; Value2: 0.2W; SizeX_mm: 1
R17 = CMP-0022448-4: RES, 49.9, 1%, 0.1 W, AEC-Q200 Grade 0, 0603; Manufacturer: Vishay-Dale; Value: 49.9; Value_Code: 49R9; Power_W: 100mW; Value2: 0.1W; VDC_V: 75V; TempCo: 100 ppm/C; EIA_Code: E96; AEC Category: Q200; AEC Grade: 0; AEC Qualified: Y; SizeArea_mm2: 1.28; SizeX_mm: 1.6; SizeY_mm: 0.8; SizeZ_mm: 1
R18 = CMP-0026490-2: RES, 61.9 k, 1%, 0.063 W, AEC-Q200 Grade 0, 0402; Manufacturer: Vishay-Dale; Power_W: 63mW; TempCo: 100 ppm/C; Value_Code: 61k9; Value: 61.9k; EIA_Code: E96; SizeX_mm: 1; SizeY_mm: 0.5; SizeZ_mm: 0.6; Value2: 0.063W; AEC Qualified: Y; VDC_V: 50V; AEC Category: Q200; AEC Grade: 0
R22 = CMP-0026403-2: RES, 49.9 k, 1%, 0.063 W, AEC-Q200 Grade 0, 0402; Manufacturer: Vishay-Dale; Power_W: 63mW; TempCo: 100 ppm/C; Value_Code: 49k9; Value: 49.9k; EIA_Code: E96; SizeX_mm: 1; SizeY_mm: 0.5; SizeZ_mm: 0.6; Value2: 0.063W; AEC Qualified: Y; VDC_V: 50V; AEC Category: Q200; AEC Grade: 0
R23 = CMP-0026742-1: RES, 6.80 k, 1%, 0.0625 W, 0402; Manufacturer: Yageo America; Power_W: 62.5mW; TempCo: 100 ppm/C; Value_Code: 6k80; U/M: EA; Value: 6.80k; Res_ohm: 6.8k; SizeX_mm: 1; SizeY_mm: 0.5; SizeZ_mm: 0.6; AEC Qualified: N; VDC_V: 50V; AEC Category: Q200
R24 = CMP-0026371-2: RES, 41.2 k, 1%, 0.063 W, AEC-Q200 Grade 0, 0402; Manufacturer: Vishay-Dale; Power_W: 63mW; TempCo: 100 ppm/C; Value_Code: 41k2; Value: 41.2k; EIA_Code: E96; SizeX_mm: 1; SizeY_mm: 0.5; SizeZ_mm: 0.6; Value2: 0.063W; AEC Qualified: Y; VDC_V: 50V; AEC Category: Q200; AEC Grade: 0
R25 = CMP-0026553-2: RES, 7.15 k, 1%, 0.063 W, AEC-Q200 Grade 0, 0402; Manufacturer: Vishay-Dale; Power_W: 63mW; TempCo: 100 ppm/C; Value_Code: 7k15; Value: 7.15k; EIA_Code: E96; SizeX_mm: 1; SizeY_mm: 0.5; SizeZ_mm: 0.6; Value2: 0.063W; AEC Qualified: Y; VDC_V: 50V; AEC Category: Q200; AEC Grade: 0
T1 T2 = CMP-0055442-1: Terminal 50A Lug; Manufacturer: Panduit; CNHeader: FALSE; Green_Lifecycle: Not Set; Cert_CULUS: Y; Green_REACh: Incomplete; Voltage_V: 600V; CompType: Screw Terminal; ContactFinish: Copper
TP1 TP3 = CMP-0055147-1: Test Point, Multipurpose, Red, TH; Manufacturer: Keystone; CNHeader: FALSE; Green_Lifecycle: Active; Green_REACh: Passed; ContactFinish: Silver; CT: TRUE
TP2 TP6 TP7 = CMP-0055148-1: Test Point, Multipurpose, Black, TH; Manufacturer: Keystone; CNHeader: FALSE; Green_Lifecycle: Active; Green_REACh: Passed; ContactFinish: Silver; CT: TRUE
TP4 TP5 = CMP-0055139-2: Test Point, Miniature, White, TH; Manufacturer: Keystone Electronics; ContactFinish: Silver; Green_REACh: Passed; CT: TRUE; Green_Lifecycle: Active; CNHeader: FALSE
U1 = CMP-0097820-2: Manufacturer: Texas Instruments; AEC Category: Q200; CompType: IC; Standoff Height: 0mm; SizeZ_mm: 0.89mm
U2 = CMP-0049938-1: Automotive, 80-V synchronous buck DC/DC controller with ultra-low IQ 24-VQFN -40 to 125; Manufacturer: Texas Instruments; SizeZ_mm: 1mm; AEC Qualified: Yes; AEC Grade: Grade 1; Max Duty Cycle: 100%; Max Supply Voltage: 80V; Min Supply Voltage: 3.5V; Nominal Supply Current: 9.5-124uA; Number Of Outputs: 1; Output Type: Fixed,AdjustableProgrammable; Output Voltage: 3.3/5/12/0.8-55V; Standoff Height: 0mm; Switching Frequency: 0.1-2.2MHz; TaMax_C: +125°C; TaMin_C: -40°C; TJmax_C: +150°C

## Sheet PMP31349_Hardware.SchDoc
size 431 x 279 mm; Date: Not shown in title block; ApprovedBy: Not shown in title block; CheckedBy: Not shown in title block; Author: Not shown in title block; CompanyName: Not shown in title block; Engineer: Not shown in title block; Organization: Not shown in title block; Address1: Not shown in title block; Address2: Not shown in title block; Address3: Not shown in title block; Address4: Not shown in title block; DocumentNumber: 3; Revision: Use project parameter SCH_Rev; SheetNumber: 2; SheetTotal: 2; PageSetup: Record=PageOptions¦CenterHorizontal=True¦CenterVertical=True¦PrintScale=1.00¦XCorrection=1.00¦YCorrection=1.00¦PrintKind=0¦BorderSize=5000000¦LeftOffset=0¦BottomOffset=0¦Orientation=2¦PaperLength=1000¦PaperWidth=1000¦Scale=100¦PaperSource=15¦PrintQuality=600¦MediaType=1¦DitherType=10¦PaperKind=Letter¦PrintScaleMode=1
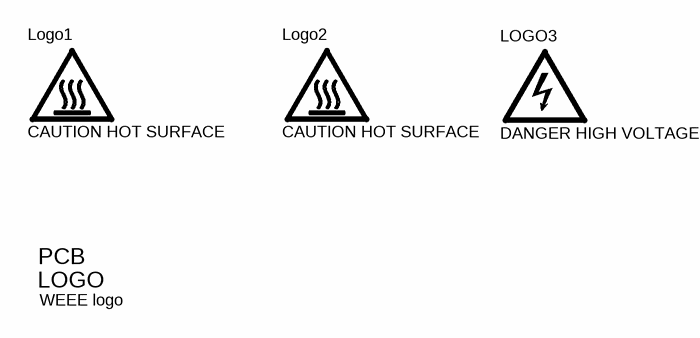
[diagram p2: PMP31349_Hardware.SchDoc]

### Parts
Logo1  CAUTION HOT SURFACE  [IEC_HotSurface_Medium]  (no BOM)
Logo2  CAUTION HOT SURFACE  [IEC_HotSurface_Small]  (no BOM)
LOGO3  DANGER HIGH VOLTAGE  [IEC_HighVoltage_Medium]  (no BOM)
Logo4  WEEE logo  [WEEE_Minimum]  (no BOM)

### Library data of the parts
Logo1 Logo2 = CMP-0074837-2: IEC 61010-1 Hot Surface Warning; Manufacturer: Texas Instruments; CompType: IC; AEC Category: Q200; SymbolCreator: a0412235
LOGO3 = CMP-0074835-1: IEC 61010-1 High Voltage Warning; SymbolCreator: a0412235
Logo4 = CMP-0074769-1

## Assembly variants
001: not fitted C46 C47 C53 C55 C58 C59 C60 C61 D1 R6 R12 R15 R16 R19 R21 R25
